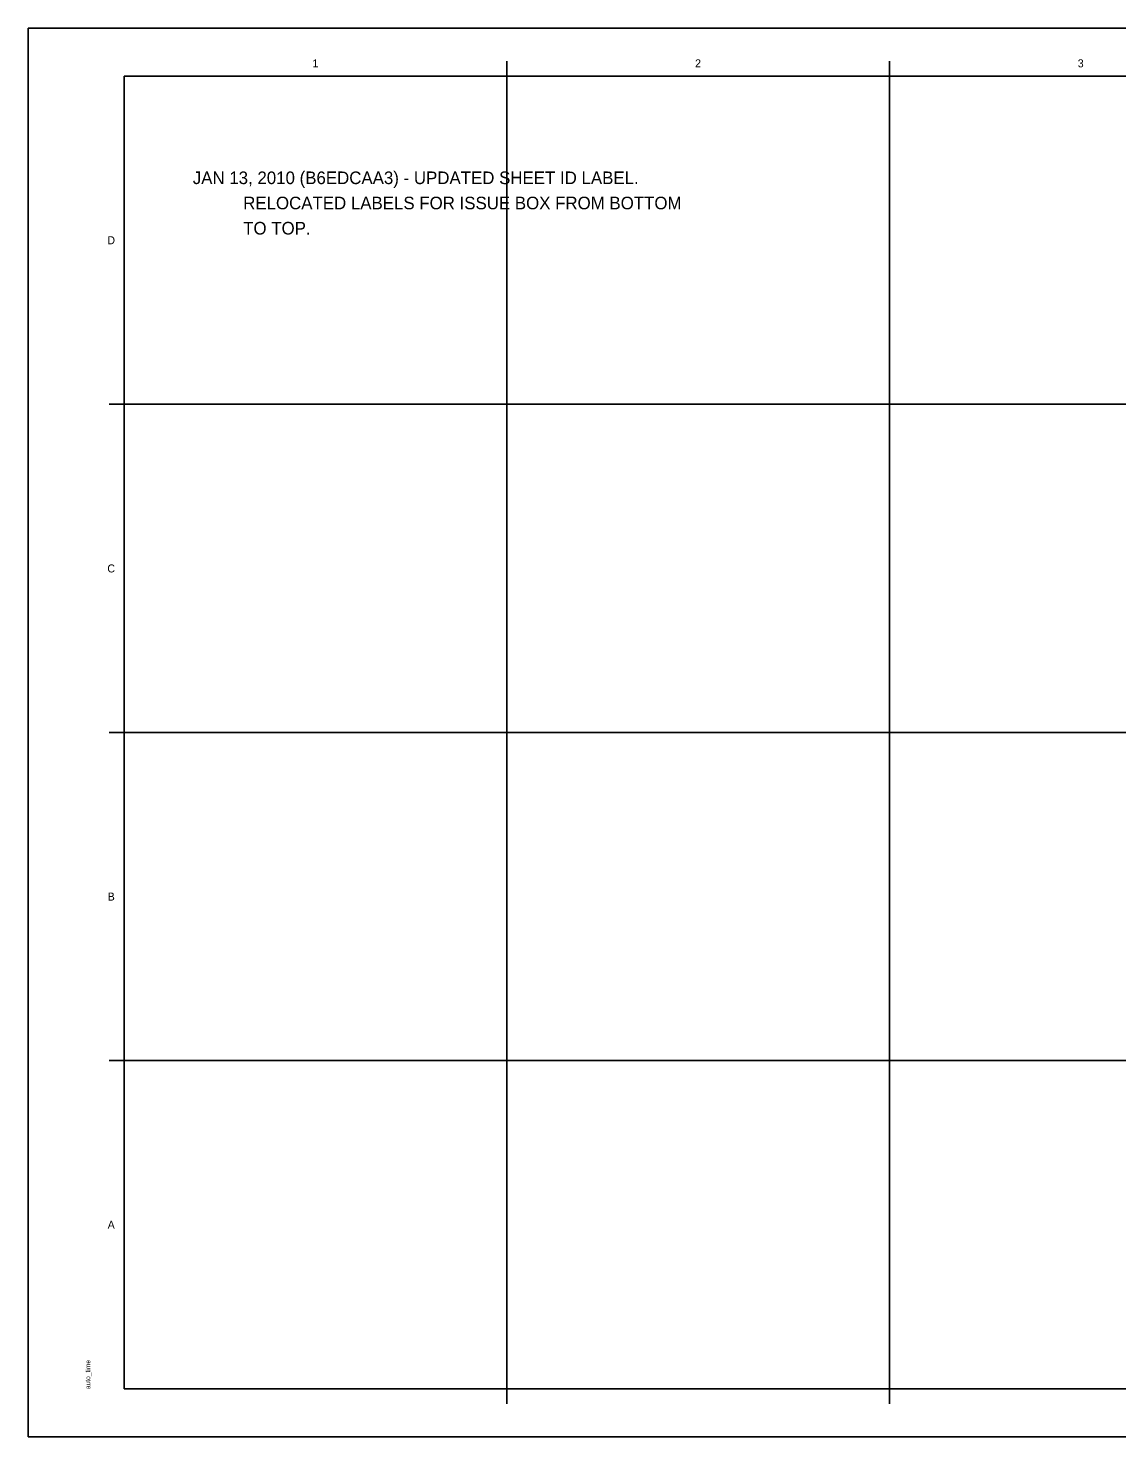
# Model space of a CAD drawing. Extents: x 0 to 2.83, y 0 to 1.83.
# Drawn here: x 0 to 1.417, y 0 to 1.833 of the extents above; entities that cross this region are included whole.
import ezdxf

# ---------------------------------------------------------------- set-up
doc = ezdxf.new("R2010")
doc.units = 0
for name, color, linetype in [('G-ANNO-NPLT', 7, 'Continuous'), ('G-ANNO-PRFL', 7, 'Continuous'), ('G-ANNO-TEXT', 7, 'Continuous'), ('G-ANNO-TEXT-AUTO', 7, 'Continuous'), ('G-ANNO-TTLB', 7, 'Continuous'), ('G-ANNO-TTLB-GRID', 7, 'Continuous')]:
    doc.layers.add(name, color=color, linetype=linetype)

msp = doc.modelspace()

# ---------------------------------------------------------------- linework, layer by layer
at = {"layer": 'G-ANNO-PRFL'}
msp.add_line((0.125, 0.9167), (2.6146, 0.9167), dxfattribs=at)
at = {"layer": 'G-ANNO-TEXT'}
for p, q in [((0.125, 1.3438), (0.1053, 1.3438)), ((0.125, 0.9167), (0.1053, 0.9167)), ((0.125, 0.4896), (0.1053, 0.4896))]:
    msp.add_line(p, q, dxfattribs=at)
at = {"layer": 'G-ANNO-TTLB'}
for p, q in [((0.6229, 1.7905), (0.6229, 1.7708)), ((1.1208, 1.7905), (1.1208, 1.7708)), ((0.6229, 0.0625), (0.6229, 0.0428)), ((1.1208, 0.0625), (1.1208, 0.0428))]:
    msp.add_line(p, q, dxfattribs=at)
for points in [[(0, 1.8333), (2.8333, 1.8333), (2.8333, 0), (0, 0)], [(0.125, 1.7708), (2.6146, 1.7708), (2.6146, 0.0625), (0.125, 0.0625)]]:
    msp.add_lwpolyline(points, close=True, dxfattribs=at)
at = {"layer": 'G-ANNO-TTLB-GRID'}
for p, q in [((0.6229, 0.0625), (0.6229, 1.7708)), ((1.1208, 0.0625), (1.1208, 1.7708)), ((2.6146, 1.3438), (0.125, 1.3438)), ((2.6146, 0.9167), (0.125, 0.9167)), ((2.6146, 0.4896), (0.125, 0.4896))]:
    msp.add_line(p, q, dxfattribs=at)

# ---------------------------------------------------------------- texts
at = {"layer": 'G-ANNO-NPLT'}
for s, height, p in [('JAN 13, 2010 (B6EDCAA3) - UPDATED SHEET ID LABEL.  ', 0.016404, (0.2142, 1.6304)), ('RELOCATED LABELS FOR ISSUE BOX FROM BOTTOM', 0.016404, (0.2798, 1.5976)), ('TO TOP.', 0.0164, (0.2798, 1.5648))]:
    msp.add_text(s, height=height, dxfattribs=at).set_placement(p)
at = {"layer": 'G-ANNO-TEXT'}
for s, p in [('1', (0.3699, 1.7824)), ('2', (0.8678, 1.7824)), ('3', (1.3658, 1.7824)), ('D', (0.103, 1.5521)), ('C', (0.103, 1.125)), ('B', (0.1034, 0.6979)), ('A', (0.1034, 0.2708))]:
    msp.add_text(s, height=0.0104, dxfattribs=at).set_placement(p)
at = {"layer": 'G-ANNO-TEXT-AUTO'}
msp.add_text('auto_time', height=0.00625, rotation=90, dxfattribs=at).set_placement((0.0808, 0.0621))

doc.saveas('drawing.dxf')
